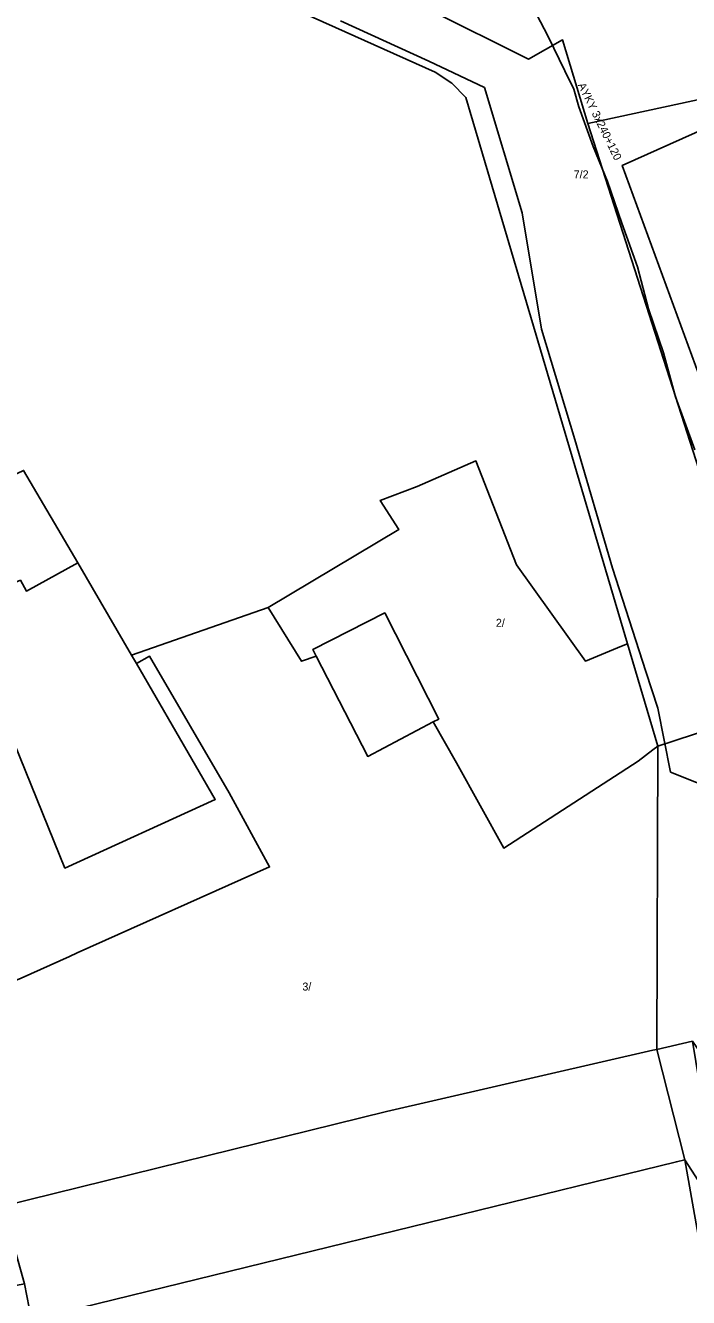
# Model space of a CAD drawing. Extents: x -793400 to -756198, y -1074141 to -1042963.
# Drawn here: x -783247 to -783184.8, y -1065351.8 to -1065232.6 of the extents above; entities that cross this region are included whole.
import ezdxf

# ---------------------------------------------------------------- set-up
doc = ezdxf.new("R2010")
doc.units = 0
for name, color, linetype in [('Parcela', 7, 'Continuous'), ('Popiskový text - Parcela', 7, 'Continuous'), ('Popiskový text - Vedení nn kabelové', 7, 'Continuous'), ('Spojnice nn', 7, 'Continuous'), ('Spojnice vn', 7, 'Continuous'), ('Stavební objekt', 7, 'Continuous'), ('Vedení 22 kV kabelové', 7, 'Continuous'), ('Vedení nn kabelové', 7, 'Continuous')]:
    doc.layers.add(name, color=color, linetype=linetype)

msp = doc.modelspace()

# ---------------------------------------------------------------- linework, layer by layer
at = {"layer": 'Parcela'}
for points in [[(-783237.43, -1065216.95), (-783199.83, -1065235.73), (-783196.65, -1065233.93), (-783194.28, -1065241.77), (-783178.12, -1065292.05), (-783173.32, -1065294.4), (-783177.68, -1065296.84), (-783187.72, -1065300.11), (-783190.56, -1065290.52), (-783205.72, -1065239.34), (-783207.03, -1065237.99), (-783208.59, -1065236.96), (-783235.05, -1065225.06), (-783238.13, -1065225.57), (-783243.03, -1065216.54), (-783256.12, -1065192.4), (-783266.62, -1065172.96), (-783272.44, -1065162), (-783267.78, -1065160.5), (-783264.5, -1065166.6)], [(-783181.91, -1065258.89), (-783172.02, -1065276.5), (-783165.93, -1065273.01), (-783161.45, -1065270.5), (-783156.73, -1065285.12), (-783173.16, -1065294.31), (-783177.67, -1065282.27), (-783191.05, -1065245.69), (-783179.76, -1065240.65), (-783170.9, -1065236.7), (-783169.84, -1065236.23), (-783169.7, -1065236.44), (-783166.69, -1065240.77), (-783174.44, -1065245.09), (-783175.41, -1065245.63), (-783183.05, -1065250.84), (-783179.51, -1065257.86)], [(-783173.16, -1065294.31), (-783173.32, -1065294.4), (-783178.12, -1065292.05), (-783194.28, -1065241.77), (-783181.69, -1065239.04), (-783170.9, -1065236.7), (-783179.76, -1065240.65), (-783191.05, -1065245.69), (-783177.67, -1065282.27)], [(-783200.95, -1065283.12), (-783194.49, -1065292.16), (-783191.11, -1065290.75), (-783190.56, -1065290.52), (-783187.72, -1065300.11), (-783188.2, -1065300.48), (-783189.56, -1065301.54), (-783202.15, -1065309.67), (-783206.57, -1065301.7), (-783208.77, -1065297.85), (-783214.9, -1065301.08), (-783219.72, -1065291.69), (-783221.1, -1065292.16), (-783224.24, -1065287.14), (-783211.97, -1065279.81), (-783213.73, -1065277.09), (-783210.27, -1065275.8), (-783204.76, -1065273.39)], [(-783237.02, -1065291.6), (-783236.57, -1065292.38), (-783235.36, -1065291.68), (-783227.89, -1065304.51), (-783224.1, -1065311.44), (-783242.12, -1065319.5), (-783242.85, -1065319.83), (-783247.38, -1065321.86), (-783248.11, -1065322.18), (-783254.93, -1065325.24), (-783257.13, -1065324.59), (-783259.32, -1065323.17), (-783261.71, -1065319.77), (-783266.86, -1065321.96), (-783267.09, -1065320.98), (-783275.21, -1065287.59), (-783247.15, -1065274.28), (-783242.05, -1065282.95)], [(-783184.48, -1065327.78), (-783181.79, -1065344.18), (-783185.2, -1065338.9), (-783187.81, -1065328.54)], [(-783291.97, -1065337.56), (-783284.45, -1065347.4), (-783273.57, -1065347.14), (-783271.05, -1065346.73), (-783255.53, -1065352.15), (-783254.94, -1065352.03), (-783247.05, -1065350.51), (-783246.4, -1065353.9), (-783185.97, -1065339.08), (-783185.2, -1065338.9), (-783177.15, -1065384.24), (-783173.84, -1065402.95), (-783217.4, -1065406.42), (-783247.51, -1065408.83), (-783317.57, -1065413.84), (-783316.17, -1065402.75), (-783315.7, -1065397.69), (-783318.45, -1065397.17), (-783318.2, -1065393.1), (-783318.13, -1065392.5), (-783314.55, -1065361.66), (-783301.1, -1065362.07)], [(-783157.6, -1065460.47), (-783162.89, -1065463.53), (-783165.88, -1065447.1), (-783168.63, -1065432.07), (-783168.72, -1065431.58), (-783169.51, -1065427.11), (-783170.4, -1065422.15), (-783173.84, -1065402.95), (-783177.15, -1065384.24), (-783185.2, -1065338.9), (-783181.79, -1065344.18), (-783177.87, -1065352.89), (-783173.97, -1065359.27), (-783158.59, -1065382.55), (-783143.17, -1065406.37), (-783139.35, -1065415.01), (-783138.56, -1065420.16), (-783138.72, -1065421.92), (-783139.66, -1065432.62), (-783144.33, -1065443.47), (-783149.56, -1065451.96)]]:
    msp.add_lwpolyline(points, close=True, dxfattribs=at)
for points in [[(-783169.31, -1065352.34), (-783175.94, -1065340.1), (-783182.62, -1065330.47), (-783184.48, -1065327.78), (-783187.81, -1065328.54), (-783187.72, -1065300.11), (-783177.68, -1065296.84), (-783173.32, -1065294.4), (-783173.16, -1065294.31), (-783156.73, -1065285.12), (-783140.65, -1065276.14), (-783135.72, -1065273.37), (-783134.47, -1065275.89), (-783125.74, -1065270.93), (-783125.51, -1065270.04), (-783124.29, -1065266.93), (-783111, -1065259.46), (-783050.92, -1065228.15), (-783004.72, -1065202.26), (-782983.18, -1065192.04), (-782974.5, -1065189.1), (-782967.33, -1065186.68)], [(-783181.56, -1065226.08), (-783181.69, -1065239.04), (-783194.28, -1065241.77), (-783196.65, -1065233.93), (-783199.83, -1065235.73), (-783237.43, -1065216.95)], [(-783297.43, -1065235.39), (-783238.13, -1065225.57), (-783235.05, -1065225.06), (-783208.59, -1065236.96), (-783207.03, -1065237.99), (-783205.72, -1065239.34), (-783190.56, -1065290.52), (-783191.11, -1065290.75), (-783194.49, -1065292.16), (-783200.95, -1065283.12), (-783204.76, -1065273.39), (-783210.27, -1065275.8), (-783213.73, -1065277.09), (-783211.97, -1065279.81), (-783224.24, -1065287.14), (-783237.02, -1065291.6), (-783242.05, -1065282.95), (-783247.15, -1065274.28)], [(-783247.38, -1065321.86), (-783242.85, -1065319.83), (-783242.12, -1065319.5), (-783224.1, -1065311.44), (-783227.89, -1065304.51), (-783235.36, -1065291.68), (-783236.57, -1065292.38), (-783237.02, -1065291.6), (-783224.24, -1065287.14), (-783221.1, -1065292.16), (-783219.72, -1065291.69), (-783214.9, -1065301.08), (-783208.77, -1065297.85), (-783206.57, -1065301.7), (-783202.15, -1065309.67), (-783189.56, -1065301.54), (-783188.2, -1065300.48), (-783187.72, -1065300.11), (-783187.81, -1065328.54), (-783185.2, -1065338.9), (-783185.97, -1065339.08), (-783246.4, -1065353.9), (-783247.05, -1065350.51)]]:
    msp.add_lwpolyline(points, dxfattribs=at)
at = {"layer": 'Spojnice nn'}
msp.add_lwpolyline([(-783199.81, -1065230.1), (-783197.99, -1065233.6), (-783196.43, -1065236.84), (-783195.59, -1065238.56), (-783195.12, -1065240.21), (-783193.78, -1065243.93), (-783192.42, -1065247.21), (-783191.08, -1065251.11), (-783189.61, -1065255.19), (-783188.58, -1065259.15), (-783187.18, -1065263.26), (-783186.06, -1065267.4), (-783184.24, -1065272.34)], dxfattribs=at)
at = {"layer": 'Spojnice vn'}
msp.add_lwpolyline([(-783217.44, -1065232.14), (-783209.16, -1065235.91), (-783203.96, -1065238.4), (-783200.42, -1065250.14), (-783198.63, -1065261.03), (-783195.48, -1065271.38), (-783191.96, -1065283.45), (-783188.85, -1065293.14), (-783187.71, -1065296.56), (-783186.53, -1065302.56), (-783179.23, -1065305.47), (-783167.3, -1065309.87), (-783165.55, -1065310.52), (-783164.11, -1065310.42), (-783160.68, -1065306.97), (-783153.73, -1065302.41), (-783137.04, -1065293.34), (-783123.72, -1065286.43), (-783109.5, -1065278.44), (-783096.64, -1065271.58), (-783083.79, -1065263.97), (-783070.55, -1065256.39), (-783062.85, -1065252.28)], dxfattribs=at)
at = {"layer": 'Stavební objekt'}
for points in [[(-783242.05, -1065282.95), (-783237.02, -1065291.6), (-783236.57, -1065292.38), (-783229.19, -1065305.11), (-783243.27, -1065311.55), (-783248.53, -1065298.6), (-783258.52, -1065304.02), (-783253.27, -1065316.03), (-783260.37, -1065319.2), (-783260.78, -1065318.28), (-783264.34, -1065310.39), (-783265.25, -1065310.8), (-783267.13, -1065306.65), (-783266.22, -1065306.24), (-783268.76, -1065294.36), (-783260.78, -1065290.34), (-783247.44, -1065284.57), (-783246.88, -1065285.59)], [(-783208.77, -1065297.85), (-783214.9, -1065301.08), (-783219.72, -1065291.69), (-783220.05, -1065291.07), (-783213.3, -1065287.63), (-783208.24, -1065297.58)], [(-783185.97, -1065339.08), (-783246.4, -1065353.9), (-783247.05, -1065350.51), (-783249.1, -1065343.25), (-783213.13, -1065334.35), (-783188.2, -1065328.63), (-783187.81, -1065328.54), (-783185.2, -1065338.9)]]:
    msp.add_lwpolyline(points, close=True, dxfattribs=at)
at = {"layer": 'Vedení 22 kV kabelové'}
msp.add_lwpolyline([(-783217.44, -1065232.14), (-783209.16, -1065235.91), (-783203.96, -1065238.4), (-783200.42, -1065250.14), (-783198.63, -1065261.03), (-783195.48, -1065271.38), (-783191.96, -1065283.45), (-783188.85, -1065293.14), (-783187.71, -1065296.56), (-783186.53, -1065302.56), (-783179.23, -1065305.47), (-783167.3, -1065309.87), (-783165.55, -1065310.52), (-783164.11, -1065310.42), (-783160.68, -1065306.97), (-783153.73, -1065302.41), (-783137.04, -1065293.34), (-783123.72, -1065286.43), (-783109.5, -1065278.44), (-783096.64, -1065271.58), (-783083.79, -1065263.97), (-783070.55, -1065256.39), (-783062.85, -1065252.28)], dxfattribs=at)
at = {"layer": 'Vedení nn kabelové'}
msp.add_lwpolyline([(-783184.24, -1065272.34), (-783186.06, -1065267.4), (-783187.18, -1065263.26), (-783188.58, -1065259.15), (-783189.61, -1065255.19), (-783191.08, -1065251.11), (-783192.42, -1065247.21), (-783193.78, -1065243.93), (-783195.12, -1065240.21), (-783195.59, -1065238.56), (-783196.43, -1065236.84), (-783197.99, -1065233.6), (-783199.81, -1065230.1)], dxfattribs=at)

# ---------------------------------------------------------------- texts
at = {"layer": 'Popiskový text - Parcela'}
for s, p in [('7/2', (-783195.6, -1065246.91)), ('2/', (-783202.89, -1065288.94)), ('3/', (-783221.02, -1065323.03))]:
    msp.add_text(s, height=0.75, dxfattribs=at).set_placement(p)
at = {"layer": 'Popiskový text - Vedení nn kabelové'}
msp.add_text('AYKY 3x240+120', height=0.75, rotation=296.0473, dxfattribs=at).set_placement((-783195.23, -1065238.16))

doc.saveas('drawing.dxf')
